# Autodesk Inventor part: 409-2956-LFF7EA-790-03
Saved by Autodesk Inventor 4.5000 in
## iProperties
Created: 2010-09
Part Number: 409-2956-LFF7EA-790-03
Cost Center: 0 lbmass
Material: A36 STEEL PLATE
Document SubType Name: Sheet Metal
Designer: S. Boerckel
Authority: 0 in^3
Mass: 2019.1 g
Surface Area: 484.956 cm^2
Volume: 256.883 cm^3
Density: 7.86 g/cm^3
Flat Pattern Width: 11.43 cm
Flat Pattern Length: 17.78 cm
Flat Pattern Area: 203.225 cm^2
Sheet Metal Rule: 1/2"Thk
Sheet Metal Width: 7.0000 in
Sheet Metal Length: 31.5000 in^2
Description: WELD PLATE
User Status: BURN/DRILL
SaveDate: 2008-01-15
SaveTime: 10:24
FileName: Sheet Metal
Wide: =<Flat Pattern Width>cm
Length: =<Flat Pattern Length>cm
Thickness: 0.5000 in
SMR: =<Sheet Metal Rule> - <Material>
Author: S. Boerckel
Revision Number: 0
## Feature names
1. Hole1
2. Plate1
